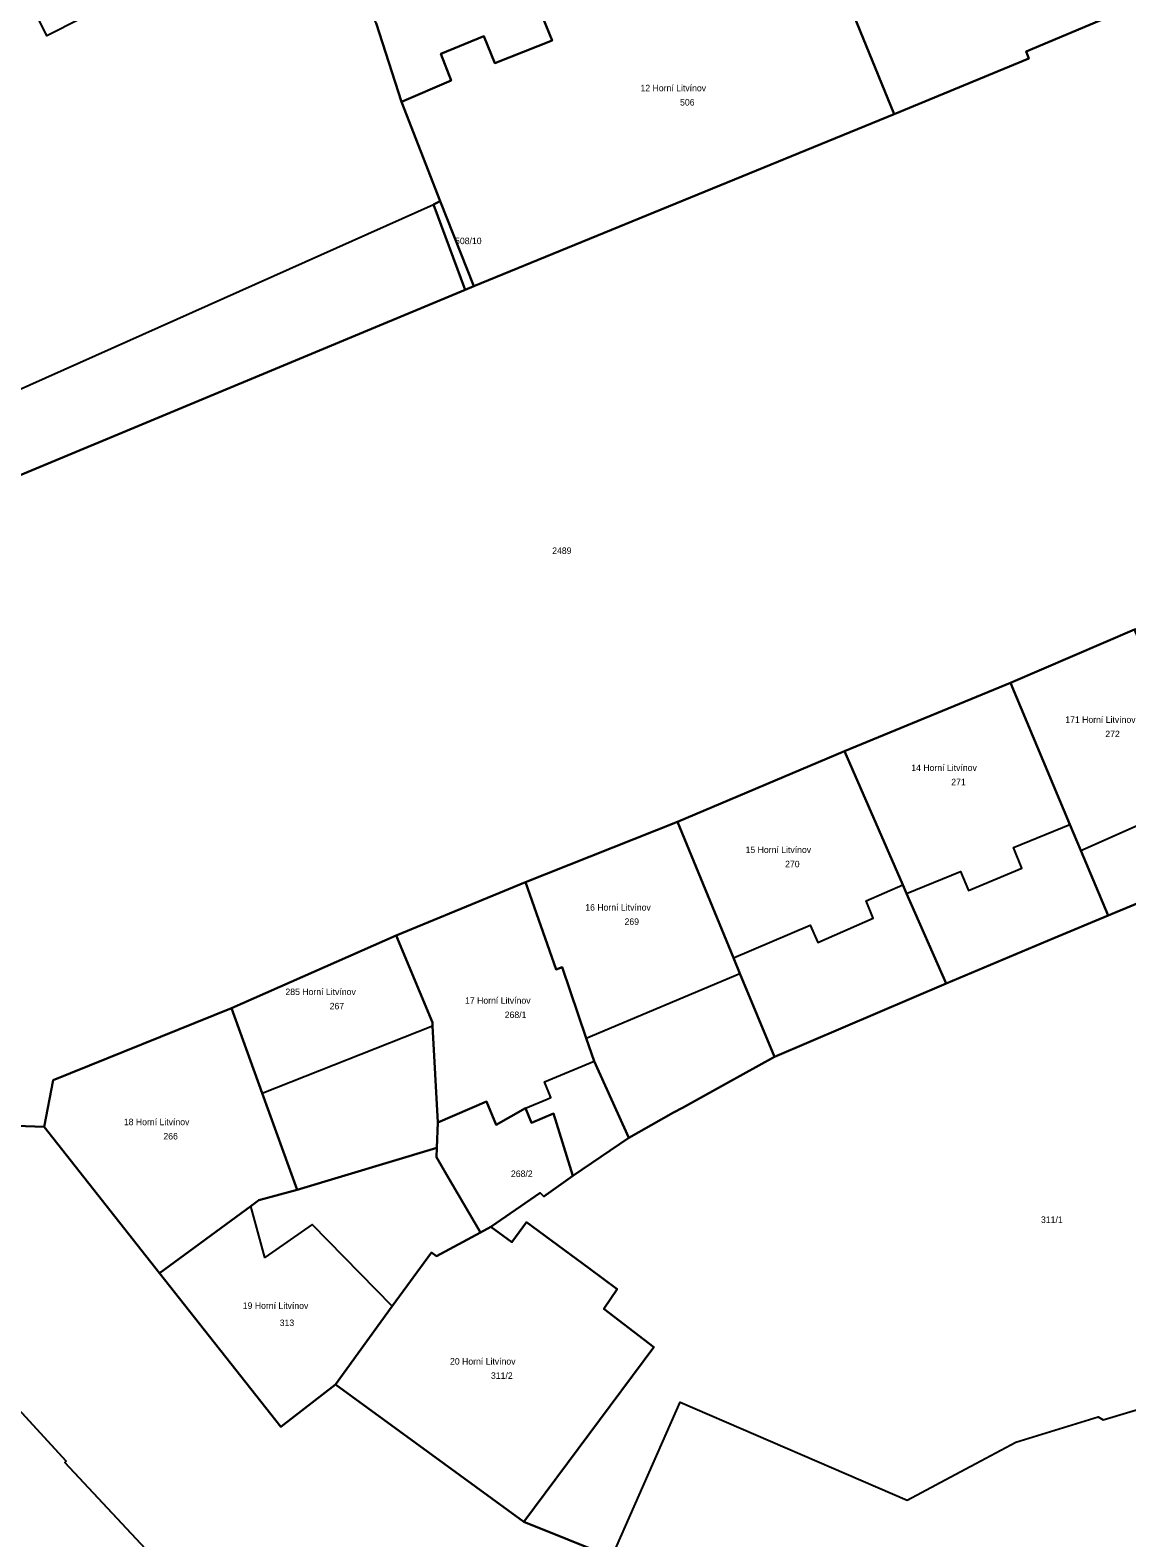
# Model space of a CAD drawing. Extents: x -792094 to -791524, y -979074 to -977761.
# Drawn here: x -791873.9 to -791789.4, y -978671 to -978554.8 of the extents above; entities that cross this region are included whole.
import ezdxf

# ---------------------------------------------------------------- set-up
doc = ezdxf.new("R2010")
doc.units = 0
doc.layers.add('katastr', color=7, linetype='Continuous')

msp = doc.modelspace()

# ---------------------------------------------------------------- linework, layer by layer
at = {"layer": 'katastr'}
for points in [[(-791875, -978589.26), (-791840.39, -978574.85), (-791842.83, -978568.27), (-791842.3, -978568.03), (-791845.28, -978560.36), (-791847.25, -978554.3), (-791851.56, -978544.62), (-791857.55, -978531.14), (-791864.51, -978515.5), (-791867.96, -978507.73), (-791867.52, -978503.3), (-791869.9, -978498.73), (-791873.83, -978489.7), (-791881.47, -978498.04)], [(-791811.16, -978551.87), (-791807.29, -978561.32), (-791796.91, -978557.01), (-791797.13, -978556.47), (-791790.51, -978553.7)], [(-791847.25, -978554.3), (-791845.28, -978560.36), (-791841.45, -978558.73), (-791842.27, -978556.66), (-791838.94, -978555.31), (-791838.1, -978557.39), (-791833.68, -978555.64), (-791834.82, -978552.82)], [(-791790.51, -978553.7), (-791797.13, -978556.47), (-791796.91, -978557.01), (-791807.29, -978561.32), (-791824.14, -978568.2), (-791839.7, -978574.57), (-791840.39, -978574.85), (-791875, -978589.26)], [(-791875, -978639.29), (-791872.85, -978639.37), (-791872.15, -978635.76), (-791858.4, -978630.22), (-791845.69, -978624.63), (-791835.74, -978620.5), (-791824.02, -978615.86), (-791811.13, -978610.41), (-791798.34, -978605.15), (-791788.78, -978601.03), (-791778.04, -978596.71), (-791762.99, -978590.52), (-791748.97, -978584.64), (-791748.21, -978584.32), (-791746.55, -978583.63), (-791746.17, -978583.47), (-791734.69, -978578.66), (-791724.47, -978574.39), (-791717.3, -978571.49), (-791702.54, -978565.36)], [(-791781.04, -978619.02), (-791790.81, -978623.08), (-791794.98, -978624.83), (-791803.3, -978628.33), (-791816.53, -978633.97), (-791820.15, -978635.97), (-791822.47, -978637.25), (-791823.62, -978637.89), (-791824.32, -978638.27), (-791827.77, -978640.22), (-791832.09, -978643.14), (-791834.32, -978644.73), (-791834.6, -978644.46), (-791838.4, -978647.07), (-791836.79, -978648.25), (-791835.66, -978646.72), (-791830.87, -978650.24), (-791828.65, -978651.87), (-791829.7, -978653.4), (-791825.83, -978656.34), (-791835.86, -978669.8), (-791829.06, -978672.54), (-791823.79, -978660.59), (-791806.31, -978668.14), (-791802.99, -978666.38), (-791801.4, -978665.53), (-791797.91, -978663.68), (-791791.58, -978661.73), (-791791.18, -978661.95), (-791778.44, -978658.12)], [(-791691.02, -978633.03), (-791709.39, -978645.99), (-791709.15, -978646.32), (-791715.04, -978650.46), (-791715.27, -978650.14), (-791727.27, -978658.6), (-791741.88, -978668.79), (-791758.03, -978673.58), (-791774.17, -978678.39), (-791785.37, -978681.63), (-791796.82, -978685.24), (-791800.29, -978685.11), (-791811.67, -978680.15), (-791829.06, -978672.54), (-791835.86, -978669.8), (-791850.39, -978659.23), (-791854.6, -978662.5), (-791863.96, -978650.65), (-791872.85, -978639.37), (-791875, -978639.29)], [(-791880.06, -978690.75), (-791862.45, -978674.63), (-791871.26, -978665.24), (-791871.15, -978665.14), (-791881.42, -978653.96)], [(-791881.42, -978653.96), (-791871.15, -978665.14), (-791871.26, -978665.24), (-791862.45, -978674.63), (-791856.94, -978677.83), (-791848.49, -978682.67), (-791846.81, -978680.56), (-791821.21, -978694.27), (-791820.82, -978694.48), (-791818.06, -978696.66), (-791815.56, -978698.63), (-791808.15, -978705.53), (-791803.72, -978710.43), (-791799.83, -978717.1), (-791797.49, -978724.11), (-791797.3, -978725.09), (-791793.68, -978725.32), (-791777.44, -978728.19), (-791768.2, -978712.08), (-791752.21, -978696.33), (-791747.66, -978693.14), (-791700.66, -978660.13)]]:
    msp.add_lwpolyline(points, dxfattribs=at)
for points in [[(-791895.64, -978523.92), (-791904.12, -978527.7), (-791898.74, -978539.79), (-791896.4, -978545.04), (-791894.73, -978548.78), (-791888.92, -978561.85), (-791886.45, -978560.75), (-791876.4, -978583.26), (-791842.83, -978568.27), (-791842.3, -978568.03), (-791845.28, -978560.36), (-791847.25, -978554.3), (-791851.56, -978544.62), (-791872.65, -978555.27), (-791887.35, -978525.65), (-791864.51, -978515.5), (-791867.96, -978507.73), (-791890.94, -978517.95), (-791889.5, -978521.19)], [(-791771.33, -978535.31), (-791774.63, -978529.81), (-791811.43, -978544.86), (-791813.62, -978545.56), (-791812.93, -978547.11), (-791811.16, -978551.87), (-791807.29, -978561.32), (-791796.91, -978557.01), (-791797.13, -978556.47), (-791790.51, -978553.7), (-791790.37, -978554.03), (-791785.57, -978552.04), (-791785.71, -978551.71), (-791779.05, -978548.94), (-791778.82, -978549.5), (-791768.52, -978545.22), (-791771.39, -978535.79), (-791771.11, -978535.68)], [(-791833.68, -978555.64), (-791838.1, -978557.39), (-791838.94, -978555.31), (-791842.27, -978556.66), (-791841.45, -978558.73), (-791845.28, -978560.36), (-791842.3, -978568.03), (-791839.7, -978574.57), (-791824.14, -978568.2), (-791807.29, -978561.32), (-791811.16, -978551.87), (-791812.93, -978547.11), (-791820.1, -978550.06), (-791821.77, -978550.75), (-791822.41, -978551.01), (-791823.58, -978548.22), (-791829.26, -978550.53), (-791834.82, -978552.82)], [(-791807.29, -978561.32), (-791811.16, -978551.87), (-791812.93, -978547.11), (-791820.1, -978550.06), (-791821.77, -978550.75), (-791822.41, -978551.01), (-791823.58, -978548.22), (-791829.26, -978550.53), (-791834.82, -978552.82), (-791833.68, -978555.64), (-791838.1, -978557.39), (-791838.94, -978555.31), (-791842.27, -978556.66), (-791841.45, -978558.73), (-791845.28, -978560.36), (-791842.3, -978568.03), (-791839.7, -978574.57), (-791824.14, -978568.2)], [(-791842.83, -978568.27), (-791840.39, -978574.85), (-791839.7, -978574.57), (-791842.3, -978568.03)], [(-791792.91, -978618.07), (-791783.25, -978613.78), (-791788.78, -978601.03), (-791798.34, -978605.15), (-791793.75, -978616.07)], [(-791790.81, -978623.08), (-791781.04, -978619.02), (-791783.25, -978613.78), (-791788.78, -978601.03), (-791798.34, -978605.15), (-791793.75, -978616.07), (-791792.91, -978618.07)], [(-791811.13, -978610.41), (-791806.63, -978620.71), (-791806.34, -978621.37), (-791802.19, -978619.69), (-791801.58, -978621.16), (-791797.46, -978619.43), (-791798.09, -978617.84), (-791793.75, -978616.07), (-791798.34, -978605.15)], [(-791790.81, -978623.08), (-791792.91, -978618.07), (-791793.75, -978616.07), (-791798.34, -978605.15), (-791811.13, -978610.41), (-791806.63, -978620.71), (-791806.34, -978621.37), (-791803.3, -978628.33), (-791794.98, -978624.83)], [(-791824.02, -978615.86), (-791819.69, -978626.35), (-791813.79, -978623.82), (-791813.2, -978625.15), (-791808.93, -978623.29), (-791809.45, -978621.94), (-791806.63, -978620.71), (-791811.13, -978610.41)], [(-791824.02, -978615.86), (-791819.69, -978626.35), (-791819.19, -978627.55), (-791816.53, -978633.97), (-791803.3, -978628.33), (-791806.34, -978621.37), (-791806.63, -978620.71), (-791811.13, -978610.41)], [(-791835.74, -978620.5), (-791833.37, -978627.25), (-791832.9, -978627.05), (-791831.04, -978632.52), (-791819.19, -978627.55), (-791819.69, -978626.35), (-791824.02, -978615.86)], [(-791820.15, -978635.97), (-791816.53, -978633.97), (-791819.19, -978627.55), (-791819.69, -978626.35), (-791824.02, -978615.86), (-791835.74, -978620.5), (-791833.37, -978627.25), (-791832.9, -978627.05), (-791831.04, -978632.52), (-791830.44, -978634.3), (-791827.77, -978640.22), (-791824.32, -978638.27), (-791823.62, -978637.89), (-791822.47, -978637.25)], [(-791842.9, -978631.58), (-791842.5, -978639.04), (-791838.74, -978637.42), (-791838, -978639.2), (-791835.73, -978637.93), (-791834.05, -978637.23), (-791833.77, -978637.11), (-791834.27, -978635.9), (-791830.44, -978634.3), (-791831.04, -978632.52), (-791832.9, -978627.05), (-791833.37, -978627.25), (-791835.74, -978620.5), (-791845.69, -978624.63), (-791842.91, -978631.32)], [(-791827.77, -978640.22), (-791830.44, -978634.3), (-791831.04, -978632.52), (-791832.9, -978627.05), (-791833.37, -978627.25), (-791835.74, -978620.5), (-791845.69, -978624.63), (-791842.91, -978631.32), (-791842.9, -978631.58), (-791842.5, -978639.04), (-791838.74, -978637.42), (-791838, -978639.2), (-791835.73, -978637.93), (-791835.26, -978639.05), (-791833.58, -978638.35), (-791832.09, -978643.14)], [(-791845.69, -978624.63), (-791858.4, -978630.22), (-791856.03, -978636.77), (-791842.9, -978631.58), (-791842.91, -978631.32)], [(-791842.57, -978640.99), (-791842.5, -978639.04), (-791842.9, -978631.58), (-791842.91, -978631.32), (-791845.69, -978624.63), (-791858.4, -978630.22), (-791856.03, -978636.77), (-791853.33, -978644.21)], [(-791856.03, -978636.77), (-791858.4, -978630.22), (-791872.15, -978635.76), (-791872.85, -978639.37), (-791863.96, -978650.65), (-791856.92, -978645.48), (-791856.29, -978645.03), (-791853.33, -978644.21)], [(-791863.96, -978650.65), (-791856.92, -978645.48), (-791856.29, -978645.03), (-791853.33, -978644.21), (-791856.03, -978636.77), (-791858.4, -978630.22), (-791872.15, -978635.76), (-791872.85, -978639.37)], [(-791842.57, -978640.99), (-791842.58, -978641.7), (-791841.81, -978643.03), (-791839.2, -978647.51), (-791838.4, -978647.07), (-791834.6, -978644.46), (-791834.32, -978644.73), (-791832.09, -978643.14), (-791833.58, -978638.35), (-791835.26, -978639.05), (-791835.73, -978637.93), (-791838, -978639.2), (-791838.74, -978637.42), (-791842.5, -978639.04)], [(-791854.6, -978662.5), (-791850.39, -978659.23), (-791846, -978653.19), (-791842.98, -978649.04), (-791842.58, -978649.34), (-791839.2, -978647.51), (-791841.81, -978643.03), (-791842.58, -978641.7), (-791842.57, -978640.99), (-791853.33, -978644.21), (-791856.29, -978645.03), (-791856.92, -978645.48), (-791863.96, -978650.65)], [(-791856.92, -978645.48), (-791863.96, -978650.65), (-791854.6, -978662.5), (-791850.39, -978659.23), (-791846, -978653.19), (-791852.18, -978646.89), (-791855.83, -978649.43)], [(-791830.87, -978650.24), (-791835.66, -978646.72), (-791836.79, -978648.25), (-791838.4, -978647.07), (-791839.2, -978647.51), (-791842.58, -978649.34), (-791842.98, -978649.04), (-791846, -978653.19), (-791850.39, -978659.23), (-791835.86, -978669.8), (-791825.83, -978656.34), (-791829.7, -978653.4), (-791828.65, -978651.87)], [(-791830.87, -978650.24), (-791835.66, -978646.72), (-791836.79, -978648.25), (-791838.4, -978647.07), (-791839.2, -978647.51), (-791842.58, -978649.34), (-791842.98, -978649.04), (-791846, -978653.19), (-791850.39, -978659.23), (-791835.86, -978669.8), (-791825.83, -978656.34), (-791829.7, -978653.4), (-791828.65, -978651.87)]]:
    msp.add_lwpolyline(points, close=True, dxfattribs=at)

# ---------------------------------------------------------------- texts
for s, p in [('12 Horní Litvínov', (-791826.86, -978559.55)), ('506', (-791823.81, -978560.65)), ('508/10', (-791841.16, -978571.33)), ('2489', (-791833.67, -978595.21)), ('171 Horní Litvínov', (-791794.11, -978608.23)), ('272', (-791791.02, -978609.33)), ('14 Horní Litvínov', (-791805.98, -978611.94)), ('271', (-791802.9, -978613.04)), ('15 Horní Litvínov', (-791818.76, -978618.26)), ('270', (-791815.71, -978619.36)), ('16 Horní Litvínov', (-791831.12, -978622.7)), ('269', (-791828.09, -978623.8)), ('285 Horní Litvínov', (-791854.24, -978629.21)), ('267', (-791850.83, -978630.31)), ('17 Horní Litvínov', (-791840.39, -978629.88)), ('268/1', (-791837.33, -978630.98)), ('18 Horní Litvínov', (-791866.7, -978639.24)), ('266', (-791863.65, -978640.34)), ('268/2', (-791836.85, -978643.23)), ('311/1', (-791795.98, -978646.77)), ('19 Horní Litvínov', (-791857.53, -978653.4)), ('313', (-791854.68, -978654.72)), ('20 Horní Litvínov', (-791841.55, -978657.69)), ('311/2', (-791838.39, -978658.79))]:
    msp.add_text(s, height=0.5, dxfattribs=at).set_placement(p)

doc.saveas('drawing.dxf')
